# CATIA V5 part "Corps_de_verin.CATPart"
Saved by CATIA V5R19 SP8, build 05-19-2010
Part number: Corps de verin
Revision: ANY
Definition: UNKNOWN
Nomenclature: Corps de vérin
Source: Unknown
Bounding box of the stored display mesh (mm): x -7.5 to 7.5, y -7.49 to 7.49, z -12 to 190
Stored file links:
  D:\Documents\1_Travail\1 - ac-limoges.fr\ac-limoges.fr\Emmanuel Maynard - STI2D_Turgot\2 -2I2D\3_SEQUENCE_Serre_Connectée\Dossier technique_SERRE\Maquettes_CATIA\Vérin_Thermodynamique\Corps_de_verin.CATPart
  D:\Documents\1_Travail\1 - ac-limoges.fr\ac-limoges.fr\Emmanuel Maynard - STI2D_Turgot\2 -2I2D\3_SEQUENCE_Serre_Connectée\Dossier technique_SERRE\Maquettes_CATIA\Vérin_Thermodynamique\Verin thermodynamique.CATProduct
  D:\Documents\1_Travail\1 - ac-limoges.fr\ac-limoges.fr\Emmanuel Maynard - STI2D_Turgot\2 -2I2D\3_SEQUENCE_Serre_Connectée\Dossier technique_SERRE\Maquettes_CATIA\Vérin_Thermodynamique\Tige_de_verin.CATPart
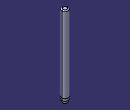
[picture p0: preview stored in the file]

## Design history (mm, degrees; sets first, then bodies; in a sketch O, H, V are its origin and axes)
Body1 "NONE" (main body)
  Solid1: solid without history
